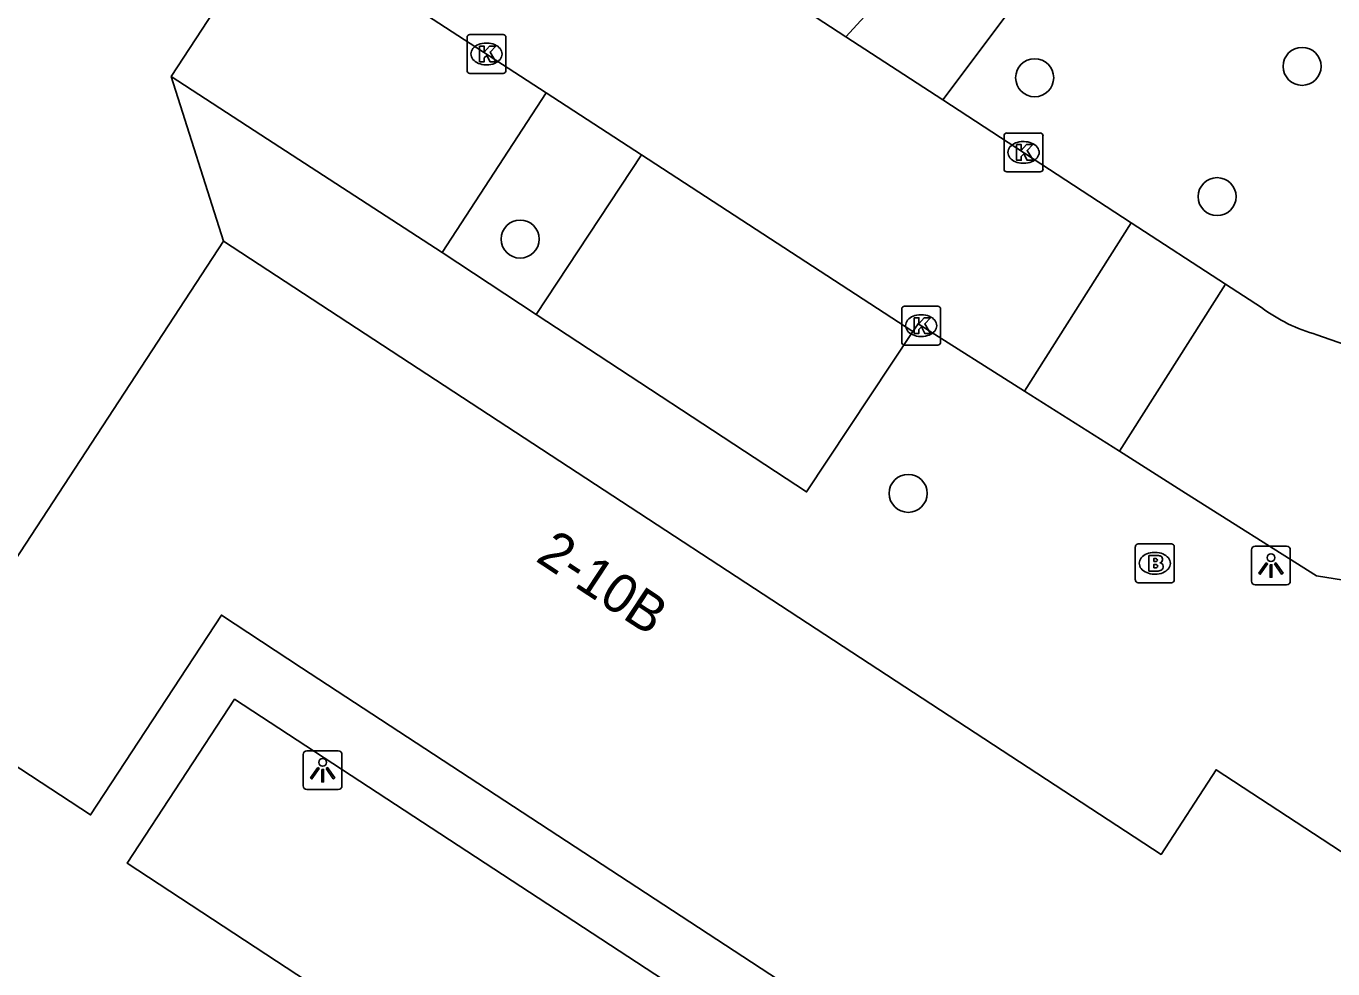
# Model space of a CAD drawing. Extents: x 159280 to 160375, y 384531 to 385872.
# Drawn here: x 159683.03 to 159716.63, y 385051.93 to 385076.18 of the extents above; entities that cross this region are included whole.
import ezdxf

# ---------------------------------------------------------------- set-up
doc = ezdxf.new("R2010")
doc.units = 0
for name, color, linetype in [('IMGEO_Boom', 7, 'Continuous'), ('IMGEO_Brandkraan', 7, 'Continuous'), ('IMGEO_Kolk', 7, 'Continuous'), ('IMGEO_Lichtpunt', 7, 'Continuous'), ('IMGEO_Pand', 7, 'Continuous'), ('IMGEO_Pand_nummerreeks', 7, 'Continuous'), ('IMGEO_Parkeervlak_open', 7, 'Continuous'), ('IMGEO_Rijbaan_lokaal_open', 7, 'Continuous'), ('IMGEO_Voetpad_halfverhard', 7, 'Continuous'), ('IMGEO_Voetpad_open', 7, 'Continuous')]:
    doc.layers.add(name, color=color, linetype=linetype)

msp = doc.modelspace()

# ---------------------------------------------------------------- linework, layer by layer
at = {"layer": 'IMGEO_Boom'}
for centre in [(159715.837, 385075.141), (159708.961, 385074.849), (159713.652, 385071.79), (159695.733, 385070.698), (159705.709, 385064.158)]:
    msp.add_circle(centre, 0.489, dxfattribs=at)
at = {"layer": 'IMGEO_Brandkraan'}
for p, q in [((159711.549, 385061.933), (159711.549, 385062.785)), ((159711.624, 385062.859), (159712.476, 385062.859)), ((159712.55, 385062.785), (159712.55, 385061.933)), ((159712.037, 385062.639), (159712.062, 385062.639)), ((159712.06, 385062.079), (159712.035, 385062.079)), ((159712.476, 385061.859), (159711.624, 385061.859))]:
    msp.add_line(p, q, dxfattribs=at)
for points in [[(159711.549, 385061.933), (159711.549, 385062.785)], [(159711.624, 385062.859), (159712.476, 385062.859)], [(159712.55, 385062.785), (159712.55, 385061.933)], [(159711.897, 385062.559), (159711.897, 385062.159), (159712.11, 385062.159)], [(159712.128, 385062.559), (159711.897, 385062.559)], [(159712.076, 385062.478), (159712.022, 385062.478), (159712.022, 385062.402)], [(159712.022, 385062.402), (159712.075, 385062.402)], [(159712.084, 385062.326), (159712.022, 385062.326), (159712.022, 385062.245)], [(159712.022, 385062.245), (159712.084, 385062.245)], [(159712.476, 385061.859), (159711.624, 385061.859)]]:
    msp.add_lwpolyline(points, dxfattribs=at)
for centre, radius, start, end in [((159711.626, 385062.783), 0.0765, 91.552, 178.448), ((159711.626, 385062.783), 0.0765, 91.552, 178.448), ((159712.474, 385062.783), 0.0765, 1.552, 88.448), ((159712.474, 385062.783), 0.0765, 1.552, 88.448), ((159712.077, 385062.44), 0.0379, 267.8285, 90.9355), ((159712.132, 385062.414), 0.145, 59.4692, 91.5367), ((159712.157, 385062.461), 0.0922, 285.5137, 58.1501), ((159712.162, 385062.269), 0.105, 301.3115, 78.989), ((159712.085, 385062.285), 0.0404, 269.8759, 90.5077), ((159712.116, 385062.41), 0.251, 268.6676, 293.5347), ((159711.626, 385061.935), 0.0765, 181.552, 268.448), ((159711.626, 385061.935), 0.0765, 181.552, 268.448), ((159712.474, 385061.935), 0.0765, 271.552, 358.448), ((159712.474, 385061.935), 0.0765, 271.552, 358.448)]:
    msp.add_arc(centre, radius, start, end, dxfattribs=at)
for centre, major_axis, ratio, start_param, end_param in [((159712.036, 385062.359), (-0.387, 0.002), 0.722429, 4.712389, 7.853982), ((159712.061, 385062.359), (-0.39, 0.002), 0.717154, 1.570796, 4.712389)]:
    msp.add_ellipse(centre, major_axis=major_axis, ratio=ratio, start_param=start_param, end_param=end_param, dxfattribs=at)
at = {"layer": 'IMGEO_Kolk'}
for p, q in [((159694.367, 385075.034), (159694.367, 385075.886)), ((159694.442, 385075.96), (159695.294, 385075.96)), ((159695.368, 385075.886), (159695.368, 385075.034)), ((159694.855, 385075.74), (159694.88, 385075.74)), ((159694.878, 385075.18), (159694.853, 385075.18)), ((159695.294, 385074.96), (159694.442, 385074.96)), ((159708.249, 385073.427), (159709.101, 385073.427)), ((159708.174, 385072.501), (159708.174, 385073.353)), ((159708.662, 385073.207), (159708.687, 385073.207)), ((159709.175, 385073.353), (159709.175, 385072.501)), ((159709.101, 385072.427), (159708.249, 385072.427)), ((159708.685, 385072.647), (159708.66, 385072.647)), ((159705.542, 385068.047), (159705.542, 385068.899)), ((159705.617, 385068.973), (159706.469, 385068.973)), ((159706.03, 385068.753), (159706.055, 385068.753)), ((159706.543, 385068.899), (159706.543, 385068.047)), ((159706.053, 385068.193), (159706.028, 385068.193)), ((159706.469, 385067.973), (159705.617, 385067.973))]:
    msp.add_line(p, q, dxfattribs=at)
for points in [[(159694.367, 385075.034), (159694.367, 385075.886)], [(159694.442, 385075.96), (159695.294, 385075.96)], [(159695.368, 385075.886), (159695.368, 385075.034)], [(159694.688, 385075.66), (159694.811, 385075.66), (159694.811, 385075.509), (159694.941, 385075.66), (159695.105, 385075.66), (159694.959, 385075.509), (159695.112, 385075.26), (159694.96, 385075.26), (159694.875, 385075.424), (159694.811, 385075.357), (159694.811, 385075.26), (159694.688, 385075.26), (159694.688, 385075.66)], [(159695.294, 385074.96), (159694.442, 385074.96)], [(159708.249, 385073.427), (159709.101, 385073.427)], [(159708.174, 385072.501), (159708.174, 385073.353)], [(159708.495, 385073.127), (159708.618, 385073.127), (159708.618, 385072.976), (159708.748, 385073.127), (159708.912, 385073.127), (159708.766, 385072.976), (159708.919, 385072.727), (159708.767, 385072.727), (159708.682, 385072.891), (159708.618, 385072.824), (159708.618, 385072.727), (159708.495, 385072.727), (159708.495, 385073.127)], [(159709.175, 385073.353), (159709.175, 385072.501)], [(159709.101, 385072.427), (159708.249, 385072.427)], [(159705.542, 385068.047), (159705.542, 385068.899)], [(159705.617, 385068.973), (159706.469, 385068.973)], [(159706.543, 385068.899), (159706.543, 385068.047)], [(159705.863, 385068.673), (159705.986, 385068.673), (159705.986, 385068.522), (159706.116, 385068.673), (159706.28, 385068.673), (159706.134, 385068.522), (159706.287, 385068.273), (159706.135, 385068.273), (159706.05, 385068.437), (159705.986, 385068.37), (159705.986, 385068.273), (159705.863, 385068.273), (159705.863, 385068.673)], [(159706.469, 385067.973), (159705.617, 385067.973)]]:
    msp.add_lwpolyline(points, dxfattribs=at)
for centre, start, end in [((159694.444, 385075.884), 91.552, 178.448), ((159694.444, 385075.884), 91.552, 178.448), ((159695.292, 385075.884), 1.552, 88.448), ((159695.292, 385075.884), 1.552, 88.448), ((159694.444, 385075.036), 181.552, 268.448), ((159694.444, 385075.036), 181.552, 268.448), ((159695.292, 385075.036), 271.552, 358.448), ((159695.292, 385075.036), 271.552, 358.448), ((159708.251, 385073.351), 91.552, 178.448), ((159708.251, 385073.351), 91.552, 178.448), ((159709.099, 385073.351), 1.552, 88.448), ((159709.099, 385073.351), 1.552, 88.448), ((159708.251, 385072.503), 181.552, 268.448), ((159708.251, 385072.503), 181.552, 268.448), ((159709.099, 385072.503), 271.552, 358.448), ((159709.099, 385072.503), 271.552, 358.448), ((159705.619, 385068.897), 91.552, 178.448), ((159705.619, 385068.897), 91.552, 178.448), ((159706.467, 385068.897), 1.552, 88.448), ((159706.467, 385068.897), 1.552, 88.448), ((159705.619, 385068.049), 181.552, 268.448), ((159705.619, 385068.049), 181.552, 268.448), ((159706.467, 385068.049), 271.552, 358.448), ((159706.467, 385068.049), 271.552, 358.448)]:
    msp.add_arc(centre, 0.0765, start, end, dxfattribs=at)
for centre, major_axis, ratio, start_param, end_param in [((159694.854, 385075.46), (-0.387, 0.002), 0.722429, 4.712389, 7.853982), ((159694.879, 385075.46), (-0.39, 0.002), 0.717154, 1.570796, 4.712389), ((159708.661, 385072.927), (-0.387, 0.002), 0.722429, 4.712389, 7.853982), ((159708.686, 385072.927), (-0.39, 0.002), 0.717154, 1.570796, 4.712389), ((159706.029, 385068.473), (-0.387, 0.002), 0.722429, 4.712389, 7.853982), ((159706.054, 385068.473), (-0.39, 0.002), 0.717154, 1.570796, 4.712389)]:
    msp.add_ellipse(centre, major_axis=major_axis, ratio=ratio, start_param=start_param, end_param=end_param, dxfattribs=at)
at = {"layer": 'IMGEO_Lichtpunt'}
for p, q in [((159714.537, 385062.705), (159714.537, 385061.898)), ((159714.537, 385062.705), (159714.537, 385061.898)), ((159715.439, 385062.8), (159714.631, 385062.8)), ((159715.439, 385062.8), (159714.631, 385062.8)), ((159715.533, 385061.898), (159715.533, 385062.705)), ((159715.533, 385061.898), (159715.533, 385062.705)), ((159714.631, 385061.804), (159715.439, 385061.804)), ((159714.631, 385061.804), (159715.439, 385061.804)), ((159690.156, 385057.44), (159690.156, 385056.633)), ((159690.156, 385057.44), (159690.156, 385056.633)), ((159691.058, 385057.535), (159690.25, 385057.535)), ((159691.058, 385057.535), (159690.25, 385057.535)), ((159691.152, 385056.633), (159691.152, 385057.44)), ((159691.152, 385056.633), (159691.152, 385057.44)), ((159690.25, 385056.539), (159691.058, 385056.539)), ((159690.25, 385056.539), (159691.058, 385056.539))]:
    msp.add_line(p, q, dxfattribs=at)
for points in [[(159714.911, 385062.369), (159714.95, 385062.341), (159714.762, 385062.079), (159714.724, 385062.106), (159714.911, 385062.369)], [(159715.123, 385062.341), (159715.161, 385062.368), (159715.348, 385062.106), (159715.309, 385062.078), (159715.123, 385062.341)], [(159715.013, 385062.321), (159715.06, 385062.321), (159715.06, 385061.999), (159715.013, 385061.999), (159715.013, 385062.321)], [(159690.53, 385057.104), (159690.569, 385057.076), (159690.381, 385056.814), (159690.343, 385056.841), (159690.53, 385057.104)], [(159690.632, 385057.056), (159690.679, 385057.056), (159690.679, 385056.734), (159690.632, 385056.734), (159690.632, 385057.056)], [(159690.742, 385057.076), (159690.78, 385057.103), (159690.967, 385056.841), (159690.928, 385056.813), (159690.742, 385057.076)]]:
    msp.add_lwpolyline(points, dxfattribs=at)
for centre in [(159715.036, 385062.503), (159690.655, 385057.238)]:
    msp.add_circle(centre, 0.0994, dxfattribs=at)
for centre, start, end in [((159714.631, 385062.705), 90, 180), ((159714.631, 385062.705), 90, 180), ((159715.439, 385062.705), 0, 90), ((159715.439, 385062.705), 0, 90), ((159714.631, 385061.898), 180, 270), ((159714.631, 385061.898), 180, 270), ((159715.439, 385061.898), 270, 0), ((159715.439, 385061.898), 270, 360), ((159690.25, 385057.44), 90, 180), ((159690.25, 385057.44), 90, 180), ((159691.058, 385057.44), 0, 90), ((159691.058, 385057.44), 0, 90), ((159690.25, 385056.633), 180, 270), ((159690.25, 385056.633), 180, 270), ((159691.058, 385056.633), 270, 0), ((159691.058, 385056.633), 270, 360)]:
    msp.add_arc(centre, 0.0946, start, end, dxfattribs=at)
at = {"layer": 'IMGEO_Pand'}
for points in [[(159680.322, 385058.747), (159688.108, 385070.646)], [(159688.108, 385070.646), (159712.21, 385054.869), (159713.626, 385057.048), (159721.603, 385051.823)], [(159715.693, 385042.917), (159713.684, 385044.233), (159713.132, 385044.595), (159714.557, 385046.77), (159711.001, 385049.098), (159709.793, 385047.246), (159709.583, 385046.927), (159709.408, 385047.042), (159690.113, 385059.669), (159688.052, 385061.026), (159684.69, 385055.888), (159680.322, 385058.747)]]:
    msp.add_lwpolyline(points, dxfattribs=at)
at = {"layer": 'IMGEO_Parkeervlak_open'}
for points in [[(159693.731, 385070.357), (159696.406, 385074.457)], [(159698.849, 385072.866), (159696.145, 385068.756)]]:
    msp.add_lwpolyline(points, dxfattribs=at)
at = {"layer": 'IMGEO_Rijbaan_lokaal_open'}
for points in [[(159691.647, 385084.031), (159698.371, 385079.646), (159704.109, 385075.904)], [(159689.447, 385078.989), (159696.406, 385074.457)], [(159706.6, 385074.279), (159704.109, 385075.904)], [(159696.406, 385074.457), (159698.849, 385072.866)], [(159706.6, 385074.279), (159711.445, 385071.119)], [(159698.849, 385072.866), (159705.83, 385068.32)], [(159711.445, 385071.119), (159708.7, 385066.788)], [(159711.445, 385071.119), (159713.866, 385069.54)], [(159713.866, 385069.54), (159711.142, 385065.24)], [(159713.866, 385069.54), (159714.791, 385068.937)], [(159708.7, 385066.788), (159705.963, 385068.522), (159705.83, 385068.32)], [(159716.218, 385068.238), (159716.929, 385067.983)], [(159711.142, 385065.24), (159708.7, 385066.788)], [(159727.505, 385060.228), (159716.203, 385062.033), (159712.839, 385064.165), (159711.142, 385065.24)], [(159704.251, 385048.484), (159688.391, 385058.861), (159685.629, 385054.646), (159701.487, 385044.232), (159704.251, 385048.484)]]:
    msp.add_lwpolyline(points, dxfattribs=at)
msp.add_arc((159717.399, 385072.455), 4.379, 233.4491, 254.356, dxfattribs=at)
at = {"layer": 'IMGEO_Voetpad_halfverhard'}
for points in [[(159704.109, 385075.904), (159707.676, 385079.805), (159711.983, 385083.022), (159712.252, 385083.418)], [(159714.859, 385081.673), (159714.61, 385081.254), (159709.953, 385078.752), (159706.6, 385074.279)]]:
    msp.add_lwpolyline(points, dxfattribs=at)
at = {"layer": 'IMGEO_Voetpad_open'}
for points in [[(159686.763, 385074.878), (159689.447, 385078.989)], [(159688.108, 385070.646), (159686.763, 385074.878)], [(159693.731, 385070.357), (159689.069, 385073.382), (159686.763, 385074.878)], [(159696.145, 385068.756), (159693.731, 385070.357)], [(159705.83, 385068.32), (159703.099, 385064.194), (159696.145, 385068.756)]]:
    msp.add_lwpolyline(points, dxfattribs=at)

# ---------------------------------------------------------------- texts
at = {"layer": 'IMGEO_Pand_nummerreeks'}
msp.add_text('2-10B', height=1, rotation=326.5908, dxfattribs=at).set_placement((159696.1, 385062.436))

doc.saveas('drawing.dxf')
